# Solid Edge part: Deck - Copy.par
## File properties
Author: morva
Template: iso metric part.par
Last saved by: morva
Revision: 72
Application: Solid Edge
Density: 2712.000 kg/m^3
Accuracy: 0.990
Username: morva
Material: Aluminum, 6061-T6
Face Style: Aluminum
Fill Style: ANSI38(Aluminum)
Virtual Style: Polished aluminum
Grouping: Metals\Aluminium Alloys
LibraryName: Materials
Coef. of Thermal Exp: 2.3e-05
Thermal Conductivity: 180.0
Specific Heat: 920.0
Modulus of Elasticity: 68947570000.0
Poisson's Ratio: 0.33
Yield Stress: 275790280.0
Ultimate Stress: 310264065.0
Elongation: 0.0
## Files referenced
..\..\DeckAssemlby.asm
C:\Users\morva\OneDrive\Dokumentumok\egyetem\VII. félév\Szakdolgozat\3D modellek\DeckAssemlby.asm
v\Szakdolgozat\3D modellek\DeckAssemlby.asm
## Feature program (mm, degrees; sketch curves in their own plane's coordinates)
sketch for "unnamed RevolvedProtrusion 1" plane through (0, 0, 0) normal (0, 0, 1) x-axis (1, 0, 0)
  line (-21, 10) -> (21, 10)
  line (21, 10) -> (21, 17.5)
  line (21, 17.5) -> (32.5, 17.5)
  line (32.5, 17.5) -> (32.5, 27.5)
  line (32.5, 27.5) -> (-32.5, 27.5)
  line (-32.5, 27.5) -> (-32.5, 17.5)
  line (-32.5, 17.5) -> (-21, 17.5)
  line (-21, 17.5) -> (-21, 10)
  dimension (linear) = 32.5
  dimension (linear) = 21
  dimension (linear) = 32.5
revolve "unnamed RevolvedProtrusion 1" add full turn 360 deg
sketch for "unnamed Protrusion 1" plane through (0, 0, 0) normal (0, -1, 0) x-axis (1, 0, 0)
  line (32.5, -17.5) -> (-32.5, -17.5)
  line (-32.5, -17.5) -> (-32.5, -27.5)
  line (-32.5, -27.5) -> (187.6352, -306.9331)
  line (205, -208.4523) -> (187.6352, -306.9331)
  line (32.5, -27.5) -> (205, -208.4523)
  line (32.5, -17.5) -> (32.5, -27.5)
  dimension (linear) = 205
  dimension (linear) = 205
  dimension (linear) = 32.5
extrude "unnamed Protrusion 1" add finite 50 symmetric
sketch for "ExtrudedProtrusion_2" plane through (191.225, 0, -286.5742) normal (0.984808, 0, -0.173648) x-axis (0.173648, 0, 0.984808)
  line (89.327, 125) -> (-910.673, 125)
  line (-910.673, 125) -> (-910.673, -125)
  line (-910.673, -125) -> (89.327, -125)
  line (89.327, -125) -> (89.327, 125)
  dimension (linear) = 910.673
  dimension (linear) = 910.673
extrude "ExtrudedProtrusion_2" add finite 50 along +normal
chamfer "Chamfer_2" setback 5
sketch for "ExtrudedCutout_1" plane through (113.0965, 0, -729.6629) normal (-0.984808, 0, 0.173648) x-axis (-0.173648, 0, -0.984808)
  line (460.749, 56) -> (380.749, 56)
  line (380.749, 56) -> (297.7866, 37.5)
  line (297.7866, 37.5) -> (297.7866, -37.5)
  line (380.749, -56) -> (297.7866, -37.5)
  line (380.749, -56) -> (460.749, -56)
  line (460.749, 56) -> (460.749, -56)
  dimension (linear) = 460.749
  dimension (linear) = 460.749
  dimension (linear) = 297.7866
  dimension (linear) = 380.749
  dimension (linear) = 380.749
  dimension (linear) = 380.749
extrude "ExtrudedCutout_1" cut finite 630.0605 symmetric
sketch for "unnamed Cutout 1" plane through (113.0965, 0, -729.6629) normal (-0.984808, 0, 0.173648) x-axis (0, -1, 0)
  line (-70, -460.749) -> (-70, -400.749)
  line (-70, -400.749) -> (-125, -264.749)
  line (-125, -264.749) -> (-125, -460.749)
  line (-125, -460.749) -> (-70, -460.749)
  dimension (linear) = 70
  dimension (linear) = 125
extrude "unnamed Cutout 1" cut through along -normal
mirror "unnamed Mirror 1" of "unnamed Cutout 1"
pattern "unnamed Pattern 1"
sketch for "unnamed Cutout 2" plane through (77.9179, 70, -1200.7104) normal (0, 1, 0) x-axis (-0.173648, 0, -0.984808)
  line (-39.251, 27.1524) -> (-9.251, 27.1524)
  line (-9.251, 17.1524) -> (-9.251, 27.1524)
  line (-39.251, 17.1524) -> (-9.251, 17.1524)
  dimension (linear) = 39.251
extrude "unnamed Cutout 2" cut through along -normal
fillet "Round_3" radius 70  Radii2 = 70 mm
fillet "Round_4" radius 5
fillet "Round_5" radius 10
fillet "Round_6" radius 10
chamfer "Chamfer_3" setback 3
sketch for "ExtrudedCutout_4" plane through (169.1528, 0, -699.6905) normal (0.984808, 0, -0.173648) x-axis (-0.173648, 0, -0.984808)
extrude "ExtrudedCutout_4" cut finite 45 along -normal
mirror "unnamed Mirror 2" of "ExtrudedCutout_4"
pattern "unnamed Pattern 2"
sketch for "ExtrudedCutout_5" plane through (169.1528, 0, -699.6905) normal (0.984808, 0, -0.173648) x-axis (-0.173648, 0, -0.984808)
  line (302.5945, -63) -> (385.6873, -48.3485)
  line (410.7298, -53.9328) -> (385.6873, -48.3485)
  line (302.5945, -73) -> (410.7298, -53.9328)
  line (302.5945, -73) -> (302.5945, -63)
  dimension (linear) = 302.5945
extrude "ExtrudedCutout_5" cut finite 25 along -normal
chamfer "Chamfer_5" setback 6
sketch for "Hole_1" plane through (178.4782, 0, -646.8037) normal (0.984808, 0, -0.173648) x-axis (0.173648, 0, 0.984808)
hole "Hole_1" diameter 8 finite  VBottomAngle = 118 deg; ThreadDepth = 20 mm
sketch for "unnamed Hole 1" plane through (178.4782, 0, -646.8037) normal (0.984808, 0, -0.173648) x-axis (0.173648, 0, 0.984808)
hole "unnamed Hole 1" finite
sketch for "unnamed Hole 2" plane through (178.4782, 0, -646.8037) normal (0.984808, 0, -0.173648) x-axis (0.173648, 0, 0.984808)
  hole centre (406.2973, 0) bore radius 3.3235
hole "unnamed Hole 2" finite
sketch for "unnamed Hole 3" plane through (178.4782, 0, -646.8037) normal (0.984808, 0, -0.173648) x-axis (0.173648, 0, 0.984808)
  hole centre (316.2973, -115) bore radius 3.3235
hole "unnamed Hole 3" finite
sketch for "unnamed Hole 4" plane through (178.4782, 0, -646.8037) normal (0.984808, 0, -0.173648) x-axis (0.173648, 0, 0.984808)
hole "unnamed Hole 4" finite
pattern "unnamed Pattern 3" of "Hole_1", "unnamed Hole 1", "unnamed Hole 2", "unnamed Hole 3", "unnamed Hole 4"
mirror "unnamed Mirror 3" of "unnamed Pattern 3" about plane through (0, 0, 0) normal (0, -1, 0)
hole "unnamed Hole 5" finite
hole "unnamed Hole 6" finite
hole "unnamed Hole 7" finite
hole "unnamed Hole 8" finite
hole "unnamed Hole 9" finite
sketch for "ExtrudedCutout_9" plane through (157.0717, 125, -632.8749) normal (0, 1, 0) x-axis (0.173648, 0, 0.984808)
  circle centre (66.2973, 3.5) radius 7.5
extrude "ExtrudedCutout_9" cut finite 18 along -normal
sketch for "unnamed Cutout 3" plane through (137.5102, 107, -747.517) normal (0, 1, 0) x-axis (0, 0, 1)
  circle centre (179.3244, 34.5207) radius 4
extrude "unnamed Cutout 3" cut through along -normal
sketch for "ExtrudedCutout_11" plane through (178.4782, 0, -646.8037) normal (0.984808, 0, -0.173648) x-axis (-0.173648, 0, -0.984808)
  line (-396.2973, 11) -> (-396.2973, -11)
  line (-396.2973, -11) -> (330.7404, -11)
  line (330.7404, -11) -> (330.7404, 11)
  line (330.7404, 11) -> (-396.2973, 11)
  dimension (linear) = 330.7404
  dimension (linear) = 396.2973
extrude "ExtrudedCutout_11" cut finite 35 along -normal
sketch for "ExtrudedCutout_12" plane through (-196.4398, 0, -239.2103) normal (0.173648, 0, 0.984808) x-axis (0, 1, 0)
  line (-13, -189.6655) -> (-13, -390)
  line (-13, -390) -> (13, -390)
  line (13, -390) -> (13, -189.6655)
  line (13, -189.6655) -> (-13, -189.6655)
  dimension (linear) = 13
extrude "ExtrudedCutout_12" cut finite 275.5902 along +normal
sketch for "ExtrudedCutout_13" plane through (0, 0, -112.2486) normal (0, 0, 1) x-axis (1, 0, 0)
  line (21.4145, 13) -> (-32.5, 13)
  line (-32.5, -13) -> (-32.5, 13)
  line (34.2642, -13) -> (-32.5, -13)
  line (34.2642, 13) -> (34.2642, -13)
  line (21.4145, 13) -> (34.2642, 13)
extrude "ExtrudedCutout_13" cut finite 85 along +normal
sketch for "unnamed Protrusion 2" plane through (86.25, -13, -167.0908) normal (0, 1, 0) x-axis (-0.173648, 0, -0.984808)
  line (-128.1365, 77.1731) -> (-126.5261, 78.3591)
  line (-126.5261, 78.3591) -> (22.5963, -124.1283)
  line (22.5963, -124.1283) -> (20.1124, -124.1283)
  line (20.1124, -124.1283) -> (-128.1365, 77.1731)
  dimension (linear) = 128.1365
extrude "unnamed Protrusion 2" add through along +normal
sketch for "unnamed Cutout 4" plane through (149.4446, 0, -609.9042) normal (0.984808, 0, -0.173648) x-axis (-0.173648, 0, -0.984808)
  line (-365, 11) -> (-325, 11)
  line (-325, 11) -> (-325, -11)
  line (-325, -11) -> (-365, -11)
  line (-365, -11) -> (-365, 11)
  dimension (linear) = 365
extrude "unnamed Cutout 4" cut through along -normal
fillet "Round_7" radius 2
fillet "Round_8" radius 2
fillet "Round_9" radius 5
sketch for "Hole_11" plane through (119.9124, 0, -691.0081) normal (-0.984808, 0, 0.173648) x-axis (-0.173648, 0, -0.984808)
  hole centre (312.0377, 0) bore radius 3.3235
hole "Hole_11" nominal diameter 8 finite  VBottomAngle = 118 deg; ThreadDepth = 9 mm
sketch for "unnamed Hole 10" plane through (119.9124, 0, -691.0081) normal (-0.984808, 0, 0.173648) x-axis (-0.173648, 0, -0.984808)
  hole centre (271.0377, 0) bore radius 3.3235
hole "unnamed Hole 10" finite
pattern "unnamed Pattern 4" of "Hole_11", "unnamed Hole 10"
sketch for "ExtrudedCutout_17" #1 plane through (169.1528, 0, -699.6905) normal (0.984808, 0, -0.173648) x-axis (-0.173648, 0, -0.984808)
sketch for "ExtrudedCutout_17" #2 plane through (169.1528, 0, -699.6905) normal (0.984808, 0, -0.173648) x-axis (-0.173648, 0, -0.984808)
extrude "ExtrudedCutout_17" cut finite 45 along -normal
fillet "unnamed Round 1"
fillet "Round_11" radius 5
extrude "ExtrudedCutout_18" cut finite 6
extrude "ExtrudedCutout_19" cut finite 35
fillet "unnamed Round 2"
chamfer "Chamfer_6" setback 20
fillet "Round_13" radius 5
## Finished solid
Body 1: solid body, 197 faces, 487 edges, 288 vertices.
  Faces by surface: plane 102, cylinder 71, cone 24
  Edges by curve: line 341, circle 142, ellipse 4
Bounding box of the edges (mm): 288.477 x 250.000 x 1219.594, from (-32.5, -125, -1192.0944) to (255.9769, 125, 27.5).
Cylindrical faces by radius (mm): R2 x2, R3.3235 x20, R4 x1, R5 x21, R6 x10, R7.5 x1, R10 x9, R17.5 x2, R27.5 x1, R62.5 x2, R70 x2
Conical faces (half-angle, radius in mm at the cone's reference point): 45 deg R2 x4, 45 deg R7 x2, 45 deg R13 x6, 45 deg R67 x2, 59 deg R3.3235 x10
Planar faces by outward normal: +x 2, +y 14, -x 2, -y 15, -z 1, oblique 68
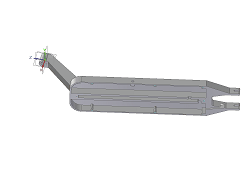
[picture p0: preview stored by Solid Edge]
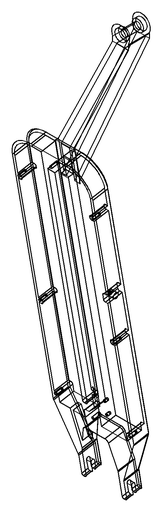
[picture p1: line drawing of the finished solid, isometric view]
